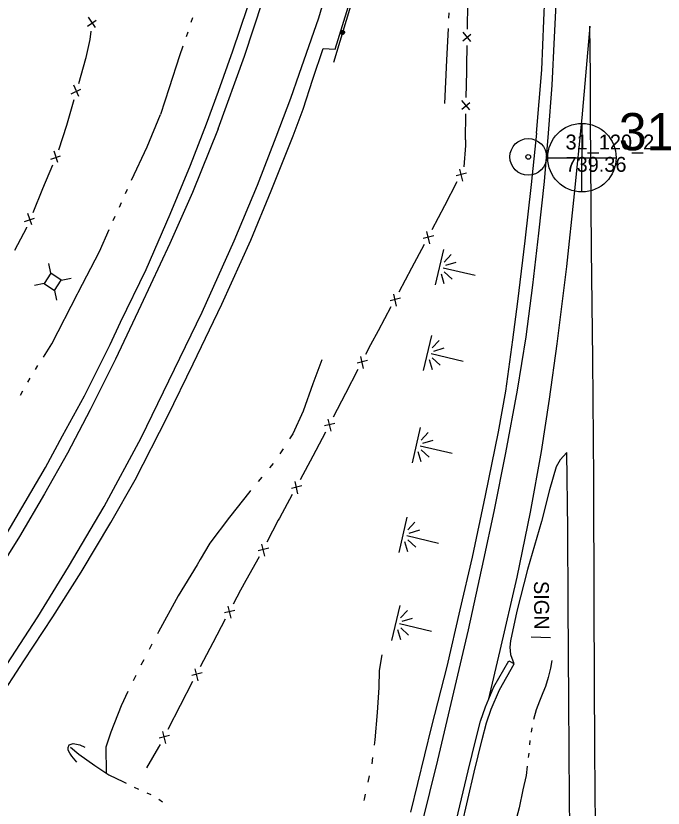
# Model space of a CAD drawing. Extents: x 589250 to 1188077, y 162953 to 363065.
# Drawn here: x 593987.7 to 594248.3, y 166364.4 to 166683.4 of the extents above; entities that cross this region are included whole.
import ezdxf

# ---------------------------------------------------------------- set-up
doc = ezdxf.new("R2010")
doc.units = 0
for name, color, linetype in [('E_BMGRD_P', 7, 'Continuous'), ('E_FEN_P', 7, 'Continuous'), ('E_MAP_PassPoints', 7, 'Continuous'), ('E_MAP_PhotoCenter', 7, 'Continuous'), ('E_RDWY', 7, 'Continuous'), ('E_RDWY_C_and_G', 7, 'Continuous'), ('E_RDWY_Gravel', 7, 'Continuous'), ('E_SGN', 7, 'Continuous'), ('E_SGN_Text', 7, 'Continuous'), ('E_UTL_AG_Bold', 7, 'Continuous'), ('E_WAL', 7, 'Continuous'), ('E_WTR_FlowLine', 7, 'Continuous'), ('E_WTR_Wetland', 7, 'Continuous')]:
    doc.layers.add(name, color=color, linetype=linetype)

# ---------------------------------------------------------------- blocks, each defined once
blk = doc.blocks.new('POINT_DISPLAY')
blk.add_line((0, 0), (0, 0))

msp = doc.modelspace()

# ---------------------------------------------------------------- linework, layer by layer
at = {"layer": 'E_BMGRD_P'}
msp.add_line((594123.25, 166690.18), (594115.6, 166664.6), dxfattribs=at)
for major_axis in [(0.142, 0.792), (0.071, 0.399)]:
    msp.add_ellipse((594119.23, 166676.74), major_axis=major_axis, ratio=0.993945, dxfattribs=at)
at = {"layer": 'E_FEN_P'}
for p, q in [((594169.49, 166678.06), (594169.61, 166688.58)), ((594016.57, 166679.34), (594020.12, 166681.75)), ((594019.81, 166678.76), (594017.02, 166682.91)), ((594017.68, 166673.96), (594018.1, 166677.29)), ((594167.71, 166673.35), (594170.87, 166676.07)), ((594170.9, 166673.15), (594167.75, 166676.85)), ((594016.06, 166666.66), (594017.68, 166673.96)), ((594169.31, 166663.34), (594169.41, 166671.55)), ((594013.1, 166656.24), (594015.96, 166666.21)), ((594015.96, 166666.21), (594016.06, 166666.66)), ((594169.26, 166661.02), (594169.31, 166663.34)), ((594169.04, 166650.5), (594169.26, 166661.02)), ((594010.05, 166652.05), (594013.93, 166653.89)), ((594013.16, 166650.98), (594011.05, 166655.51)), ((594008.25, 166639.38), (594011.24, 166649.79)), ((594167.22, 166645.81), (594170.41, 166648.5)), ((594170.41, 166645.58), (594167.3, 166649.31)), ((594168.68, 166633.47), (594168.9, 166643.99)), ((594005.03, 166629.48), (594008.25, 166639.38)), ((594168.72, 166631.26), (594168.02, 166622.63)), ((594168.68, 166633.47), (594168.72, 166631.26)), ((594004.65, 166624.39), (594003.14, 166628.96)), ((594001.8, 166625.76), (594005.71, 166627.09)), ((593998.67, 166613.87), (594002.69, 166623.48)), ((594166.28, 166621.74), (594167.45, 166616.86)), ((594169.12, 166620.06), (594164.94, 166619.04)), ((594165.29, 166616.56), (594160.25, 166606.93)), ((593994.65, 166604.27), (593998.67, 166613.87)), ((594160.25, 166606.93), (594155.21, 166597.31)), ((593991.28, 166600.61), (593995.19, 166601.93)), ((593994.13, 166599.24), (593992.62, 166603.8)), ((593987.33, 166589.1), (593992.12, 166598.21)), ((593992.12, 166598.21), (593992.17, 166598.32)), ((594153.08, 166596.53), (594154.25, 166591.65)), ((594155.92, 166594.85), (594151.74, 166593.82)), ((594152.08, 166591.35), (594146.97, 166581.76)), ((594146.97, 166581.76), (594141.87, 166572.17)), ((594139.74, 166571.41), (594140.87, 166566.52)), ((594142.57, 166569.71), (594138.38, 166568.71)), ((594138.71, 166566.23), (594133.6, 166556.64)), ((594133.6, 166556.64), (594130.55, 166550.92)), ((594130.55, 166550.92), (594128.54, 166547.03)), ((594129.26, 166544.58), (594125.08, 166543.54)), ((594126.41, 166546.25), (594127.6, 166541.37)), ((594125.44, 166541.06), (594120.43, 166531.42)), ((594120.43, 166531.42), (594115.42, 166521.78)), ((594116.14, 166519.32), (594111.97, 166518.28)), ((594113.3, 166521), (594114.48, 166516.12)), ((594112.32, 166515.81), (594108.5, 166508.46)), ((594107.28, 166506.18), (594102.14, 166496.61)), ((594108.5, 166508.46), (594107.28, 166506.18)), ((594102.83, 166494.15), (594098.64, 166493.16)), ((594100.01, 166495.86), (594101.12, 166490.97)), ((594098.96, 166490.69), (594093.82, 166481.11)), ((594093.82, 166481.11), (594093.37, 166480.28)), ((594093.37, 166480.28), (594088.8, 166471.48)), ((594089.52, 166469.02), (594085.34, 166467.99)), ((594086.67, 166470.7), (594087.85, 166465.82)), ((594085.68, 166465.52), (594080.36, 166456.05)), ((594080.36, 166456.05), (594078.18, 166452.17)), ((594078.18, 166452.17), (594075.19, 166446.49)), ((594073.07, 166445.72), (594074.22, 166440.83)), ((594075.9, 166444.03), (594071.72, 166443.01)), ((594072.06, 166440.54), (594067, 166430.92)), ((594067, 166430.92), (594063.25, 166423.79)), ((594063.25, 166423.79), (594061.96, 166421.3)), ((594059.84, 166420.51), (594061.03, 166415.63)), ((594062.69, 166418.84), (594058.51, 166417.8)), ((594058.87, 166415.32), (594053.88, 166405.67)), ((594053.88, 166405.67), (594048.88, 166396.02)), ((594046.76, 166395.24), (594047.95, 166390.36)), ((594049.61, 166393.57), (594045.44, 166392.52)), ((594045.22, 166388.95), (594040.34, 166380.65)), ((594045.79, 166390.05), (594045.22, 166388.95))]:
    msp.add_line(p, q, dxfattribs=at)
at = {"layer": 'E_MAP_PassPoints'}
for radius in [7.38, 7.38, 0.945, 0.945]:
    msp.add_circle((594193.98, 166626.63), radius, dxfattribs=at)
at = {"layer": 'E_MAP_PhotoCenter'}
for p, q in [((594215.54, 166640.12), (594215.47, 166612.71)), ((594215.54, 166640.12), (594215.47, 166612.71)), ((594201.85, 166626.31), (594229.31, 166626.3)), ((594201.85, 166626.31), (594229.31, 166626.3))]:
    msp.add_line(p, q, dxfattribs=at)
msp.add_circle((594215.59, 166626.32), 13.78, dxfattribs=at)
msp.add_circle((594215.59, 166626.32), 13.78, dxfattribs=at)
at = {"layer": 'E_RDWY'}
for p, q in [((594109.66, 166682.68), (594115.56, 166701.98)), ((594204.56, 166674.82), (594205.49, 166694.82)), ((594079.83, 166667.21), (594087.14, 166689.55)), ((594101.82, 166659.99), (594109.66, 166682.68)), ((594218.75, 166679.34), (594215.58, 166642.41)), ((594219.1, 166659.5), (594218.75, 166679.34)), ((594203.56, 166655.49), (594204.56, 166674.82)), ((594069.19, 166637.99), (594079.83, 166667.21)), ((594098.4, 166650.33), (594101.82, 166659.99)), ((594219.06, 166642.2), (594219.1, 166659.5)), ((594202.1, 166636.2), (594203.56, 166655.49)), ((594092.57, 166634.75), (594098.4, 166650.33)), ((594215.58, 166642.41), (594212.52, 166611.82)), ((594219.49, 166589.54), (594219.06, 166642.2)), ((594069.19, 166637.99), (594058.83, 166612.36)), ((594084.99, 166615.24), (594092.57, 166634.75)), ((594200.47, 166616.73), (594202.1, 166636.2)), ((594075.58, 166592.84), (594084.99, 166615.24)), ((594198.26, 166595.97), (594200.47, 166616.73)), ((594058.83, 166612.36), (594049.73, 166591.76)), ((594212.52, 166611.82), (594209.38, 166582.49)), ((594195.85, 166574.95), (594198.26, 166595.97)), ((594062.74, 166564.1), (594075.58, 166592.84)), ((594049.73, 166591.76), (594038.03, 166566.84)), ((594219.93, 166545.23), (594219.49, 166589.54)), ((594209.38, 166582.49), (594205.46, 166551.42)), ((594193.1, 166554.11), (594195.85, 166574.95)), ((594038.03, 166566.84), (594027.81, 166545.16)), ((594038.21, 166513.45), (594062.74, 166564.1)), ((594189.7, 166532.74), (594193.1, 166554.11)), ((594205.46, 166551.42), (594202.41, 166529.04)), ((594027.81, 166545.16), (594017.71, 166524.75)), ((594220.43, 166496.84), (594219.93, 166545.23)), ((594185.02, 166507.4), (594189.7, 166532.74)), ((594202.41, 166529.04), (594199.13, 166507.94)), ((594017.71, 166524.75), (594008.56, 166507.29)), ((594023.27, 166485.87), (594038.21, 166513.45)), ((594008.56, 166507.29), (593999.33, 166490.9)), ((594180.25, 166483.86), (594185.02, 166507.4)), ((594199.13, 166507.94), (594194.7, 166483.6)), ((594220.57, 166445.78), (594220.43, 166496.84)), ((593999.33, 166490.9), (593989.24, 166473.76)), ((594008.95, 166461.52), (594023.27, 166485.87)), ((594176.07, 166464.48), (594180.25, 166483.86)), ((594194.7, 166483.6), (594189.37, 166457.39)), ((593989.24, 166473.76), (593974.83, 166450.81)), ((594169.97, 166436.18), (594176.07, 166464.48)), ((593996.64, 166441.4), (594008.95, 166461.52)), ((594189.37, 166457.39), (594182.48, 166427.8)), ((594220.82, 166387.43), (594220.57, 166445.78)), ((593980.45, 166416.82), (593996.64, 166441.4)), ((594163.02, 166406.46), (594169.97, 166436.18)), ((594182.48, 166427.8), (594177.91, 166407.87)), ((594157.63, 166383.71), (594163.02, 166406.46)), ((594221.11, 166344.13), (594220.82, 166387.43)), ((594151.16, 166357.61), (594157.63, 166383.71))]:
    msp.add_line(p, q, dxfattribs=at)
at = {"layer": 'E_RDWY_C_and_G'}
for p, q in [((594180.19, 166413.19), (594186.11, 166423.76)), ((594186.11, 166423.76), (594188.2, 166422.58)), ((594182.44, 166412.08), (594188.29, 166422.53)), ((594176.75, 166405.18), (594180.19, 166413.19)), ((594179.09, 166404.28), (594182.44, 166412.08)), ((594174.77, 166399.42), (594176.75, 166405.18)), ((594177.17, 166398.7), (594179.09, 166404.28)), ((594172.98, 166392.59), (594174.77, 166399.42)), ((594175.4, 166391.99), (594177.17, 166398.7)), ((594169.84, 166379.41), (594172.98, 166392.59)), ((594172.27, 166378.84), (594175.4, 166391.99)), ((594162.57, 166348.83), (594169.84, 166379.41)), ((594165, 166348.24), (594172.27, 166378.84))]:
    msp.add_line(p, q, dxfattribs=at)
at = {"layer": 'E_RDWY_Gravel'}
for p, q in [((594116.24, 166669.97), (594126.92, 166704.32)), ((594200.27, 166681.5), (594201.04, 166702.43)), ((594075.09, 166669.32), (594080.96, 166686.8)), ((594199.41, 166661.64), (594200.27, 166681.5)), ((594069.26, 166653.1), (594075.09, 166669.32)), ((594107.24, 166657.98), (594111.47, 166670.34)), ((594111.47, 166670.34), (594116.24, 166669.97)), ((594197.35, 166636.13), (594199.41, 166661.64)), ((594103.34, 166645.9), (594107.24, 166657.98)), ((594064.42, 166640.01), (594069.26, 166653.1)), ((594099.31, 166635.17), (594103.34, 166645.9)), ((594058, 166623.26), (594064.42, 166640.01)), ((594090.57, 166612.97), (594099.31, 166635.17)), ((594197.35, 166636.13), (594195.21, 166615.57)), ((594049.89, 166603.62), (594058, 166623.26)), ((594195.21, 166615.57), (594192.62, 166592.88)), ((594082.28, 166593.14), (594090.57, 166612.97)), ((594040.22, 166581.27), (594049.89, 166603.62)), ((594070.59, 166567.29), (594082.28, 166593.14)), ((594192.62, 166592.88), (594189.6, 166568.37)), ((594029.86, 166560.06), (594040.22, 166581.27)), ((594059.08, 166543.25), (594070.59, 166567.29)), ((594189.6, 166568.37), (594187.64, 166553.03)), ((594025.65, 166551.03), (594029.86, 166560.06)), ((594015.35, 166530.48), (594025.65, 166551.03)), ((594187.64, 166553.03), (594184.83, 166532.33)), ((594048.78, 166522.1), (594059.08, 166543.25)), ((594184.83, 166532.33), (594181.81, 166515.98)), ((594006.58, 166514.37), (594015.35, 166530.48)), ((594035.75, 166496.56), (594048.78, 166522.1)), ((594181.81, 166515.98), (594176.67, 166490.23)), ((593999.7, 166501.49), (594006.58, 166514.37)), ((594209.55, 166507.57), (594206.79, 166504.59)), ((594209.97, 166476.77), (594209.55, 166507.57)), ((594206.79, 166504.59), (594205.16, 166501.82)), ((593987.92, 166481.46), (593999.7, 166501.49)), ((594205.16, 166501.82), (594202.5, 166492.62)), ((594025.93, 166479.42), (594035.75, 166496.56)), ((594176.67, 166490.23), (594171.45, 166465.48)), ((594202.5, 166492.62), (594199.29, 166479.87)), ((593980.89, 166469.78), (593987.92, 166481.46)), ((594014.02, 166459.38), (594025.93, 166479.42)), ((594199.29, 166479.87), (594193.72, 166460.53)), ((594210.05, 166446.42), (594209.97, 166476.77)), ((594171.45, 166465.48), (594166.43, 166444.28)), ((594002.61, 166441.42), (594014.02, 166459.38)), ((594193.72, 166460.53), (594189.37, 166443.69)), ((594210.33, 166407.39), (594210.05, 166446.42)), ((594166.43, 166444.28), (594161.18, 166421.47)), ((594189.37, 166443.69), (594186.82, 166431.75)), ((593990.92, 166423.73), (594002.61, 166441.42)), ((594186.82, 166431.75), (594186.52, 166429.21)), ((594186.52, 166429.21), (594186.84, 166426.2)), ((594186.84, 166426.2), (594188.2, 166422.58)), ((593979.37, 166405.83), (593990.92, 166423.73)), ((594161.18, 166421.47), (594155.08, 166397.38)), ((594210.55, 166368.09), (594210.33, 166407.39)), ((594155.08, 166397.38), (594146.54, 166362.76)), ((594210.84, 166337.35), (594210.55, 166368.09))]:
    msp.add_line(p, q, dxfattribs=at)
at = {"layer": 'E_SGN'}
msp.add_line((594195.21, 166433.42), (594202.9, 166433.14), dxfattribs=at)
at = {"layer": 'E_UTL_AG_Bold'}
for p, q in [((594001.87, 166579.77), (594001.08, 166583.7)), ((594001.87, 166579.77), (593999.11, 166575.61)), ((594006.04, 166577.01), (594001.87, 166579.77)), ((594003.28, 166572.84), (594006.04, 166577.01)), ((594006.04, 166577.01), (594009.96, 166577.81)), ((593999.11, 166575.61), (593995.19, 166574.81)), ((593999.11, 166575.61), (594003.28, 166572.84)), ((594003.28, 166572.84), (594004.08, 166568.92))]:
    msp.add_line(p, q, dxfattribs=at)
at = {"layer": 'E_WAL'}
for p, q in [((594008.77, 166388.76), (594009.22, 166389.84)), ((594008.78, 166387.76), (594008.77, 166388.76)), ((594009.22, 166389.84), (594010.75, 166390.47)), ((594010.75, 166390.47), (594013.5, 166389.91)), ((594013.5, 166389.91), (594015.52, 166389)), ((594009.47, 166386.57), (594008.78, 166387.76)), ((594010.23, 166385.31), (594009.47, 166386.57)), ((594012.34, 166382.94), (594010.23, 166385.31))]:
    msp.add_line(p, q, dxfattribs=at)
at = {"layer": 'E_WTR_FlowLine'}
for p, q in [((594058.89, 166682.57), (594058.23, 166680.69)), ((594162, 166684.58), (594161.91, 166682.49)), ((594161.72, 166678.32), (594161.14, 166665.56)), ((594056.92, 166676.92), (594056.26, 166675.03)), ((594054.94, 166671.26), (594053.57, 166667.33)), ((594053.57, 166667.33), (594049.48, 166654.44)), ((594161.14, 166665.56), (594160.3, 166648.11)), ((594049.48, 166654.44), (594045.97, 166643.75)), ((594040.56, 166630.7), (594045.97, 166643.75)), ((594034.36, 166617.3), (594040.56, 166630.7)), ((594031.86, 166611.87), (594032.69, 166613.68)), ((594029.4, 166606.42), (594030.21, 166608.24)), ((594026.96, 166600.97), (594027.77, 166602.79)), ((594021.38, 166588.48), (594025.33, 166597.33)), ((594012.81, 166571.97), (594021.38, 166588.48)), ((594002.24, 166551.42), (594012.54, 166571.44)), ((594012.54, 166571.44), (594012.81, 166571.97)), ((593998.81, 166546.04), (594002.24, 166551.42)), ((594110.9, 166544.92), (594107.3, 166535.31)), ((593995.59, 166541), (593996.66, 166542.68)), ((593992.54, 166535.87), (593993.53, 166537.59)), ((594107.3, 166535.31), (594103.4, 166524.28)), ((593989.56, 166530.68), (593990.55, 166532.41)), ((594103.4, 166524.28), (594099.2, 166515.12)), ((594099.2, 166515.12), (594097.89, 166513.1)), ((594095.3, 166509.11), (594094.01, 166507.12)), ((594091.3, 166503.22), (594089.79, 166501.39)), ((594086.77, 166497.72), (594085.25, 166495.89)), ((594081.92, 166491.86), (594073.8, 166481.5)), ((594082.23, 166492.23), (594081.92, 166491.86)), ((594073.8, 166481.5), (594065.88, 166471.02)), ((594065.88, 166471.02), (594061.94, 166464.44)), ((594060.67, 166462.31), (594053.11, 166449.83)), ((594061.94, 166464.44), (594060.67, 166462.31)), ((594053.11, 166449.83), (594045.19, 166435.4)), ((594045.19, 166435.4), (594044.76, 166434.59)), ((594042.53, 166430.39), (594041.42, 166428.29)), ((594039.2, 166424.09), (594038.08, 166421.99)), ((594134.15, 166419.75), (594135.18, 166426.11)), ((594203.49, 166423.82), (594202.94, 166420.8)), ((594202.94, 166420.8), (594202.06, 166416.98)), ((594035.98, 166417.73), (594034.94, 166415.59)), ((594133.92, 166412.99), (594134.15, 166419.75)), ((594202.06, 166416.98), (594200.98, 166413.35)), ((594032.86, 166411.32), (594030.08, 166405.62)), ((594133.35, 166402.89), (594133.92, 166412.99)), ((594199.82, 166410.79), (594198.54, 166407.5)), ((594200.98, 166413.35), (594199.82, 166410.79)), ((594198.54, 166407.5), (594197.12, 166404)), ((594030.08, 166405.62), (594025.91, 166394.92)), ((594197.12, 166404), (594196.11, 166400.11)), ((594132.39, 166391.85), (594133.35, 166402.89)), ((594025.91, 166394.92), (594024, 166388.94)), ((594195.48, 166396.73), (594195.16, 166395.03)), ((594132.11, 166389.76), (594132.39, 166391.85)), ((594194.66, 166391.63), (594194.5, 166389.91)), ((594009.73, 166388.96), (594013.12, 166386.07)), ((594024, 166388.94), (594023.92, 166385.2)), ((594013.12, 166386.07), (594019.48, 166381.56)), ((594023.92, 166385.2), (594024.03, 166382.53)), ((594131.11, 166382.27), (594131.44, 166384.77)), ((594194.07, 166385.57), (594193.98, 166384.77)), ((594194.16, 166386.49), (594194.07, 166385.57)), ((594019.48, 166381.56), (594025.22, 166377.84)), ((594024.03, 166382.53), (594024.04, 166378.6)), ((594193.58, 166381.35), (594193.13, 166377.53)), ((594025.22, 166377.84), (594031.08, 166374.99)), ((594129.5, 166374.89), (594130.06, 166377.35)), ((594193.13, 166377.53), (594191.82, 166371.76)), ((594031.08, 166374.99), (594032.1, 166374.49)), ((594035.4, 166372.86), (594037.06, 166372.04)), ((594040.41, 166370.51), (594042.12, 166369.81)), ((594128.02, 166367.98), (594128.44, 166369.97)), ((594191.82, 166371.76), (594190.33, 166364.46)), ((594045.29, 166367.99), (594046.78, 166366.9)), ((594127.91, 166367.51), (594128.02, 166367.98)), ((594190.33, 166364.46), (594188.26, 166356.98))]:
    msp.add_line(p, q, dxfattribs=at)
at = {"layer": 'E_WTR_Wetland'}
for p, q in [((594159.82, 166589.34), (594156.51, 166575.16)), ((594162.96, 166587.33), (594160.14, 166584.26)), ((594160.78, 166583), (594164.97, 166584.25)), ((594160.19, 166575.47), (594159.02, 166579.47)), ((594172.6, 166578.85), (594159.74, 166581.85)), ((594160.16, 166580.31), (594163.35, 166577.34)), ((594155.02, 166554.77), (594151.71, 166540.6)), ((594158.16, 166552.76), (594155.34, 166549.7)), ((594155.98, 166548.44), (594160.17, 166549.68)), ((594155.39, 166540.9), (594154.22, 166544.9)), ((594167.8, 166544.29), (594154.94, 166547.29)), ((594155.36, 166545.75), (594158.55, 166542.78)), ((594150.53, 166517.67), (594147.22, 166503.5)), ((594153.67, 166515.66), (594150.84, 166512.6)), ((594151.49, 166511.34), (594155.67, 166512.58)), ((594163.3, 166507.19), (594150.45, 166510.19)), ((594150.9, 166503.8), (594149.72, 166507.8)), ((594150.86, 166508.65), (594154.06, 166505.68)), ((594145.14, 166481.5), (594141.83, 166467.32)), ((594148.28, 166479.48), (594145.46, 166476.42)), ((594146.1, 166475.16), (594150.29, 166476.4)), ((594145.51, 166467.62), (594144.34, 166471.62)), ((594157.92, 166471.01), (594145.06, 166474.01)), ((594145.48, 166472.47), (594148.67, 166469.5)), ((594142.29, 166446.03), (594138.98, 166431.85)), ((594145.43, 166444.01), (594142.61, 166440.95)), ((594143.26, 166439.69), (594147.44, 166440.93)), ((594142.67, 166432.15), (594141.49, 166436.15)), ((594155.07, 166435.54), (594142.21, 166438.54)), ((594142.63, 166437), (594145.83, 166434.03))]:
    msp.add_line(p, q, dxfattribs=at)

# ---------------------------------------------------------------- block references
at = {"layer": 'E_WTR_Wetland', "rotation": 103.14131956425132}
for p in [(594158.26, 166582.68), (594158.14, 166582.14), (594158.15, 166582.2), (594159.74, 166581.85), (594160.96, 166581.57), (594153.34, 166547.58), (594153.35, 166547.64), (594153.46, 166548.12), (594154.94, 166547.29), (594156.16, 166547), (594148.85, 166510.48), (594148.86, 166510.54), (594148.97, 166511.01), (594150.45, 166510.19), (594151.67, 166509.9), (594143.46, 166474.3), (594143.47, 166474.36), (594143.58, 166474.84), (594145.06, 166474.01), (594146.28, 166473.72), (594140.74, 166439.37), (594140.61, 166438.83), (594140.63, 166438.89), (594142.21, 166438.54), (594143.44, 166438.25)]:
    msp.add_blockref('POINT_DISPLAY', p, dxfattribs=at)

# ---------------------------------------------------------------- texts
at = {"layer": 'E_MAP_PassPoints'}
for s, p in [('31_120_2', (594208.98, 166629.62)), ('31_120_2', (594208.98, 166629.62)), ('739.36', (594208.98, 166620.62)), ('739.36', (594208.98, 166620.62))]:
    msp.add_text(s, height=6, dxfattribs=at).set_placement(p)
at = {"layer": 'E_MAP_PhotoCenter'}
msp.add_text('31_120', height=15, dxfattribs=at).set_placement((594230.44, 166629.29))
msp.add_text('31_120', height=15, dxfattribs=at).set_placement((594230.44, 166629.29))
at = {"layer": 'E_SGN_Text'}
msp.add_text('SIGN', height=6, rotation=270.4034, dxfattribs=at).set_placement((594196.28, 166455.85))

doc.saveas('drawing.dxf')
